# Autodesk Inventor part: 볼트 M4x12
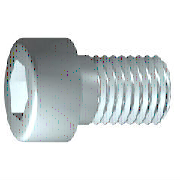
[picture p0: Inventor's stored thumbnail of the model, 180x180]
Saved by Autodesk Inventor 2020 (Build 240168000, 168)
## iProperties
IsCustomPart: 0
Created: 2012-02
Part Number: 볼트 M4x12
Material: 강철, 연강
Description: 6각 소켓 머리 캡 나사
Document SubType Name: Modeling
Standard: ISO 4762
Designer: mduedu
Standard Revision: Fourth edition 2004-03-01
Standards Organization: ISO
Language: ko-KR
Size Designation: M4 x 12
Categories: <MemberInstance><Categories><Category DisplayName="조임쇠" InternalName="e4da775c-781d-43d5-af7c-5136215cf5a6" Mnemonic="FSTN"><Category DisplayName="볼트" InternalN
Density: 7.75 g/cm^3
Appearance: 강철
Author: mduedu
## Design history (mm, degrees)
sketch "스케치1"
  geometry: L1 (-1, 0)-(12, 0); L2 (12, 0)-(12, 2); L3 (12, 2)-(1.75, 2); L4 (1.75, 2)-(1.32, 2); L5 (1.32, 2)-(0, 2); L6 (0, 2)-(0, 3.5); L7 (0, 3.5)-(-4, 3.5); L8 (-4, 3.5)-(-4, 1.732); L9 (-4, 1.732)-(-2, 1.732); L10 (-2, 1.732)-(-1, 0); L11 (-7.2, 0)-(15.2, 0) reference; L12 (0, -0.7)-(0, 4.2) reference; L13 (1.75, 2)-(0, 2)
  constraints: 22 end point, 6 parallel, 2 collinear, 2 perpendicular, 1 horizontal, 1 point on line
  dimensions: "d1" = 10.25 distance from line of L3.end L2 (= GEL); "d2" = 0.42952 distance of L4.end L3.end (computed from GAL); "d3" = 4 distance between parallel lines of L8 L6 (= KOH); "d4" = 2 distance of L8.end L9.end (= INTI); "d5" = 60 deg angle of L10 L1; "d6" = 4 diameter of L3 L1 (= GD); "d7" = 4 diameter of L5 L1 (= BDM); "d8" = 3.4641 diameter of L9 L1 (= 1.1547 x SW); "d9" = 7 diameter of L7 L1 (= KOD); "d26" = 12 distance between parallel lines of L12 L2 (= NLG)
revolve "본체" sketch "스케치1" stored, may be unused: angle "d10" = 90 deg
sketch "스케치2"
  geometry: L1 (0, -4.9)-(0, 4.9) reference; L2 (-4.9, 0)-(4.9, 0) reference; L3 (1.732, 0)-(0.866, -1.5); L4 (0.866, -1.5)-(-0.866, -1.5); L5 (-0.866, -1.5)-(-1.732, 0); L6 (-1.732, 0)-(-0.866, 1.5); L7 (-0.866, 1.5)-(0.866, 1.5); L8 (0.866, 1.5)-(1.732, 0); 2 further points
  constraints: 12 end point, 1 coincident, 1 horizontal alignment, 1 point on line, 12 other
extrude "슬롯" join sketch "스케치2" stored distance "d11" = 10; taper "d12" = 0 deg
workplane "Work Plane1"
fillet "Fillet2" dims "d30" = 0.1 (= R)
body "Solid1"
fillet "모깎기1" dims "d17" = 0.4 (= RR)
feature "스레드" dims "d13" = 10.25 (= GEL), "d14" = 0
chamfer "모따기1" distance "d15" = 0.42941 (= -0.5 x SPD + 0.5 x GD); stored, may be unused: second distance "d16" = 0.42941 (= GUL), angle "d27" = 45 deg
other parameters: "GD" = 4 [user parameter; used in 2 equation terms], "NLG" = 12 [user parameter; used in 1 equation term], "GEL" = 10.25 [user parameter; used in 2 equation terms], "KOD" = 7 [user parameter; used in 1 equation term], "KOH" = 4 [user parameter; used in 1 equation term], "INTI" = 2 [user parameter; used in 1 equation term], "GAL" = 0.42941 (= 0.61345 x PTC) [user parameter; used in 1 equation term], "GUL" = 0.42941 (= 0.61345 x PTC) [user parameter; used in 1 equation term], "BDM" = 4 (= NND) [user parameter; used in 1 equation term], "SW" = 3 [user parameter; used in 2 equation terms], "RR" = 0.4 [user parameter; used in 1 equation term], "SPD" = 3.14117 (= NND - 1.2269 x PTC) [user parameter; used in 1 equation term], "d19" = 0, "d28" = 0, "d29" = 0, "R" = 0.1 [user parameter; used in 1 equation term], "TOA" = 30 deg [user parameter], "GD1" = 3.14117 (= THREADDIA - 1.2269 x PTC) [user parameter], "THREADDIA" = 4 [user parameter; used in 1 equation term], "FAWI" = 45 deg [user parameter], "TPU" = 14.28571 (computed from PTC) [user parameter], "PTC" = 0.7 [user parameter; used in 5 equation terms], "NND" = 4 [user parameter; used in 2 equation terms], "E0" = 3.465 (= 1.155 x SW) [user parameter]
